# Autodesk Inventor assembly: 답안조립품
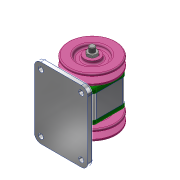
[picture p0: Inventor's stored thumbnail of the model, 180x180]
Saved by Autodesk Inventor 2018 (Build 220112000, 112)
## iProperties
Created: 2020-11
Part Number: 답안조립품
Document SubType Name: Assembly
Designer: Administrator
Author: Administrator
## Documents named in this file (10)
- C:\Users\Administrator\Desktop\701106V1050\답안조립품.iam
- C:\Users\Administrator\Desktop\701106V1050\본체.ipt
- C:\Users\Administrator\Desktop\701106V1050\축.ipt
- C:\Users\Administrator\Desktop\701106V1050\베어링 6004.ipt
- C:\Users\Administrator\Desktop\701106V1050\커버.ipt
- C:\Users\Administrator\Desktop\701106V1050\오일 실 17 30 5.ipt
- C:\Users\Administrator\Desktop\701106V1050\키 5 x 5 x 12.ipt
- C:\Users\Administrator\Desktop\701106V1050\V-벨트풀리.ipt
- C:\Users\Administrator\Desktop\701106V1050\너트 M10x1.ipt
- C:\Users\Administrator\Desktop\701106V1050\볼트 M4.ipt
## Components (2 placed, 1 different names)
1. V-벨트풀리:1
2. V-벨트풀리:2
